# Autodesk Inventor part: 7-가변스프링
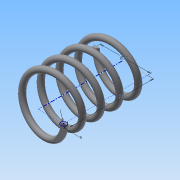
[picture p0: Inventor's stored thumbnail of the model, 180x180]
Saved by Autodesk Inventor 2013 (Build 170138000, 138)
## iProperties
Created: 2015-03
Part Number: 7-가변스프링
Material: 강철, 탄소
Document SubType Name: Modeling
Designer: Administrator
Density: 7.87 g/cm^3
Mass: 48.2733 g
Surface Area: 62.0009 cm^2
Volume: 6.13384 cm^3
Author: Administrator
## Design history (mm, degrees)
sketch "스케치1"
  geometry: L1 (0, 0)-(17.5, 0); L2 (17.5, 0)-(17.5, 43.5); L3 (17.5, 43.5)-(0, 43.5); L4 (0, 43.5)-(0, 0); C1 r 2 at (17.5, 0)
  constraints: 8 end point, 2 parallel, 1 centre point, 1 coincident, 1 horizontal, 1 perpendicular
  dimensions: "d0" = 4 diameter of C1; "d2" = 35 diameter of L2 L4; "d3" = 43.5 distance of L1.end L2.end (derived)
feature "코일1" pitch "d4" = 10; turns "d6" = 4.5; dims "d5" = 43.5 (= d3), "d7" = 0, angle "d8" = 90 deg, angle "d9" = 90 deg, "d10" = 0, "d11" = 0
sketch "스케치2"
  geometry: L1 (-19.5, 0)-(-15.5, 0) reference; 1 further point
  constraints: 1 horizontal alignment
extrude "돌출1" cut sketch "스케치2" stored distance "d12" = 10; taper "d13" = 0 deg
node "작업 평면1"
sketch "스케치3"
  geometry: L1 (-19.5, 0)-(-15.5, 0) reference; 1 further point
  constraints: 1 horizontal alignment
extrude "돌출2" cut sketch "스케치3" stored distance "d15" = 10; taper "d16" = 0 deg
node "솔리드1"
node "절단 모서리 투영1"
node "절단 모서리 투영2"
other parameters: "d14" = -43.5 (= -d3)
